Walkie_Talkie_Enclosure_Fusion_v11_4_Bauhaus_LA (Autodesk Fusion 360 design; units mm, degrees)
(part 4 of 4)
sketch "Action Button Retaining Ring" plane through (0, 0, 0) normal (0, 0, 1) x axis (1, 0, 0)
  line L1 (4.3, -61.5) -> (-4.3, -61.5)
  line L2 (14.5, -42.7) -> (14.5, -51.3)
  line L3 (-4.3, -32.5) -> (4.3, -32.5)
  line L4 (-14.5, -51.3) -> (-14.5, -42.7)
  line L5 (4.55, -58.8) -> (-4.55, -58.8)
  line L6 (11.8, -42.45) -> (11.8, -51.55)
  line L7 (-4.55, -35.2) -> (4.55, -35.2)
  line L8 (-11.8, -51.55) -> (-11.8, -42.45)
  arc A1 centre (4.3, -51.3) radius 10.2 clockwise from (14.5, -51.3) to (4.3, -61.5)
  arc A2 centre (4.3, -42.7) radius 10.2 clockwise from (4.3, -32.5) to (14.5, -42.7)
  arc A3 centre (-4.3, -42.7) radius 10.2 clockwise from (-14.5, -42.7) to (-4.3, -32.5)
  arc A4 centre (-4.3, -51.3) radius 10.2 clockwise from (-4.3, -61.5) to (-14.5, -51.3)
  arc A5 centre (4.55, -51.55) radius 7.25 clockwise from (11.8, -51.55) to (4.55, -58.8)
  arc A6 centre (4.55, -42.45) radius 7.25 clockwise from (4.55, -35.2) to (11.8, -42.45)
  arc A7 centre (-4.55, -42.45) radius 7.25 clockwise from (-11.8, -42.45) to (-4.55, -35.2)
  arc A8 centre (-4.55, -51.55) radius 7.25 clockwise from (-4.55, -58.8) to (-11.8, -51.55)
extrude "Extrude3" add sketch "Action Button Retaining Ring" blind 0.5 from offset 2.3
sketch "Sketch4" plane through (0, 0, 0) normal (0, 0, 1) x axis (1, 0, 0)
  circle C1 centre (0, -47) radius 2.5
extrude "Extrude4" add sketch "Sketch4" blind 0.4 from offset 2.25
sketch "Raised Action Mark" plane through (0, 0, 0) normal (0, 0, 1) x axis (1, 0, 0)
  line L1 (3.4, -42.8) -> (3.4, -51.2)
  line L2 (-4.2, -47) -> (3.4, -42.8)
  line L3 (3.4, -51.2) -> (-4.2, -47)
extrude "Extrude5" cut sketch "Raised Action Mark" blind 0.42 from offset -0.6
sketch "Status Light Diffuser Sketch" plane through (0, 0, 0) normal (0, 0, 1) x axis (1, 0, 0)
  line L1 (0.05, 0.1) -> (-0.05, 0.1)
  line L2 (1.9, 8.05) -> (1.9, 1.95)
  line L3 (-0.05, 9.9) -> (0.05, 9.9)
  line L4 (-1.9, 1.95) -> (-1.9, 8.05)
  arc A1 centre (0.05, 1.95) radius 1.85 clockwise from (1.9, 1.95) to (0.05, 0.1)
  arc A2 centre (0.05, 8.05) radius 1.85 clockwise from (0.05, 9.9) to (1.9, 8.05)
  arc A3 centre (-0.05, 8.05) radius 1.85 clockwise from (-1.9, 8.05) to (-0.05, 9.9)
  arc A4 centre (-0.05, 1.95) radius 1.85 clockwise from (-0.05, 0.1) to (-1.9, 1.95)
extrude "Extrude1" new body sketch "Status Light Diffuser Sketch" blind 2.82 from offset -0.42
fillet "Fillet1" radius 0.65
sketch "Status Light Collector Sketch" plane through (0, 0, 0) normal (0, 0, 1) x axis (1, 0, 0)
  circle C1 centre (0, 5) radius 2.7
extrude "Extrude2" add sketch "Status Light Collector Sketch" blind 1.35 from offset 2.15
sketch "Front Switch Clamp Plate Sketch" plane through (0, 0, 0) normal (0, 0, 1) x axis (1, 0, 0)
  line L1 (17, -54) -> (-17, -54)
  line L2 (20, -43) -> (20, -51)
  line L3 (-17, -40) -> (17, -40)
  line L4 (-20, -51) -> (-20, -43)
  line L5 (3, -50.5) -> (-3, -50.5)
  line L6 (4.5, -45) -> (4.5, -49)
  line L7 (-3, -43.5) -> (3, -43.5)
  line L8 (-4.5, -49) -> (-4.5, -45)
  arc A1 centre (17, -51) radius 3 clockwise from (20, -51) to (17, -54)
  arc A2 centre (17, -43) radius 3 clockwise from (17, -40) to (20, -43)
  arc A3 centre (-17, -43) radius 3 clockwise from (-20, -43) to (-17, -40)
  arc A4 centre (-17, -51) radius 3 clockwise from (-17, -54) to (-20, -51)
  arc A5 centre (3, -49) radius 1.5 clockwise from (4.5, -49) to (3, -50.5)
  arc A6 centre (3, -45) radius 1.5 clockwise from (3, -43.5) to (4.5, -45)
  arc A7 centre (-3, -45) radius 1.5 clockwise from (-4.5, -45) to (-3, -43.5)
  arc A8 centre (-3, -49) radius 1.5 clockwise from (-3, -50.5) to (-4.5, -49)
extrude "Extrude1" new body sketch "Front Switch Clamp Plate Sketch" blind 1.4 from offset 10.9
sketch "Front Switch Corner Guide Sketch" plane through (0, 0, 0) normal (0, 0, 1) x axis (1, 0, 0)
  line L1 (-6.65, -55) -> (-7.55, -55)
  line L2 (-6.2, -53.65) -> (-6.2, -54.55)
  line L3 (-7.55, -53.2) -> (-6.65, -53.2)
  line L4 (-8, -54.55) -> (-8, -53.65)
  arc A1 centre (-6.65, -54.55) radius 0.45 clockwise from (-6.2, -54.55) to (-6.65, -55)
  arc A2 centre (-6.65, -53.65) radius 0.45 clockwise from (-6.65, -53.2) to (-6.2, -53.65)
  arc A3 centre (-7.55, -53.65) radius 0.45 clockwise from (-8, -53.65) to (-7.55, -53.2)
  arc A4 centre (-7.55, -54.55) radius 0.45 clockwise from (-7.55, -55) to (-8, -54.55)
extrude "Extrude2" add sketch "Front Switch Corner Guide Sketch" blind 7.25 from offset 3.65
sketch "Front Switch Corner Guide Sketch (1)" plane through (0, 0, 0) normal (0, 0, 1) x axis (1, 0, 0)
  line L1 (-6.65, -40.8) -> (-7.55, -40.8)
  line L2 (-6.2, -39.45) -> (-6.2, -40.35)
  line L3 (-7.55, -39) -> (-6.65, -39)
  line L4 (-8, -40.35) -> (-8, -39.45)
  arc A1 centre (-6.65, -40.35) radius 0.45 clockwise from (-6.2, -40.35) to (-6.65, -40.8)
  arc A2 centre (-6.65, -39.45) radius 0.45 clockwise from (-6.65, -39) to (-6.2, -39.45)
  arc A3 centre (-7.55, -39.45) radius 0.45 clockwise from (-8, -39.45) to (-7.55, -39)
  arc A4 centre (-7.55, -40.35) radius 0.45 clockwise from (-7.55, -40.8) to (-8, -40.35)
extrude "Extrude3" add sketch "Front Switch Corner Guide Sketch (1)" blind 7.25 from offset 3.65
sketch "Front Switch Corner Guide Sketch (2)" plane through (0, 0, 0) normal (0, 0, 1) x axis (1, 0, 0)
  line L1 (7.55, -55) -> (6.65, -55)
  line L2 (8, -53.65) -> (8, -54.55)
  line L3 (6.65, -53.2) -> (7.55, -53.2)
  line L4 (6.2, -54.55) -> (6.2, -53.65)
  arc A1 centre (7.55, -54.55) radius 0.45 clockwise from (8, -54.55) to (7.55, -55)
  arc A2 centre (7.55, -53.65) radius 0.45 clockwise from (7.55, -53.2) to (8, -53.65)
  arc A3 centre (6.65, -53.65) radius 0.45 clockwise from (6.2, -53.65) to (6.65, -53.2)
  arc A4 centre (6.65, -54.55) radius 0.45 clockwise from (6.65, -55) to (6.2, -54.55)
extrude "Extrude4" add sketch "Front Switch Corner Guide Sketch (2)" blind 7.25 from offset 3.65
sketch "Front Switch Corner Guide Sketch (3)" plane through (0, 0, 0) normal (0, 0, 1) x axis (1, 0, 0)
  line L1 (7.55, -40.8) -> (6.65, -40.8)
  line L2 (8, -39.45) -> (8, -40.35)
  line L3 (6.65, -39) -> (7.55, -39)
  line L4 (6.2, -40.35) -> (6.2, -39.45)
  arc A1 centre (7.55, -40.35) radius 0.45 clockwise from (8, -40.35) to (7.55, -40.8)
  arc A2 centre (7.55, -39.45) radius 0.45 clockwise from (7.55, -39) to (8, -39.45)
  arc A3 centre (6.65, -39.45) radius 0.45 clockwise from (6.2, -39.45) to (6.65, -39)
  arc A4 centre (6.65, -40.35) radius 0.45 clockwise from (6.65, -40.8) to (6.2, -40.35)
extrude "Extrude5" add sketch "Front Switch Corner Guide Sketch (3)" blind 7.25 from offset 3.65
sketch "Front Switch Clamp M2 Clearance Sketch" plane through (0, 0, 0) normal (0, 0, 1) x axis (1, 0, 0)
  circle C1 centre (-17, -47) radius 1.3
extrude "Extrude6" cut sketch "Front Switch Clamp M2 Clearance Sketch" blind 2.2 from offset 10.5
sketch "Front Switch Clamp M2 Clearance Sketch (1)" plane through (0, 0, 0) normal (0, 0, 1) x axis (1, 0, 0)
  circle C1 centre (17, -47) radius 1.3
extrude "Extrude7" cut sketch "Front Switch Clamp M2 Clearance Sketch (1)" blind 2.2 from offset 10.5
sketch "LEFT PTT BUTTON Cap Sketch" plane through (0, 0, 0) normal (1, 0, 0) x axis (0, 0, -1)
  line L1 (-14.65, -15) -> (-14.85, -15)
  line L2 (-8.75, 33.1) -> (-8.75, -9.1)
  line L3 (-14.85, 39) -> (-14.65, 39)
  line L4 (-20.75, -9.1) -> (-20.75, 33.1)
  arc A1 centre (-14.65, -9.1) radius 5.9 clockwise from (-8.75, -9.1) to (-14.65, -15)
  arc A2 centre (-14.65, 33.1) radius 5.9 clockwise from (-14.65, 39) to (-8.75, 33.1)
  arc A3 centre (-14.85, 33.1) radius 5.9 clockwise from (-20.75, 33.1) to (-14.85, 39)
  arc A4 centre (-14.85, -9.1) radius 5.9 clockwise from (-14.85, -15) to (-20.75, -9.1)
extrude "Extrude1" new body sketch "LEFT PTT BUTTON Cap Sketch" blind -1.7 (= "-( 1.70 mm )") from offset 41
fillet "Fillet1" radius 1.2
sketch "LEFT PTT BUTTON End Guide Shoe Sketch" plane through (0, 0, 0) normal (1, 0, 0) x axis (0, 0, -1)
  line L1 (-10.95, -8.6) -> (-18.55, -8.6)
  line L2 (-10.45, -7.9) -> (-10.45, -8.1)
  line L3 (-18.55, -7.4) -> (-10.95, -7.4)
  line L4 (-19.05, -8.1) -> (-19.05, -7.9)
  arc A1 centre (-10.95, -8.1) radius 0.5 clockwise from (-10.45, -8.1) to (-10.95, -8.6)
  arc A2 centre (-10.95, -7.9) radius 0.5 clockwise from (-10.95, -7.4) to (-10.45, -7.9)
  arc A3 centre (-18.55, -7.9) radius 0.5 clockwise from (-19.05, -7.9) to (-18.55, -7.4)
  arc A4 centre (-18.55, -8.1) radius 0.5 clockwise from (-18.55, -8.6) to (-19.05, -8.1)
extrude "Extrude2" add sketch "LEFT PTT BUTTON End Guide Shoe Sketch" blind 3 from offset 36.5
sketch "LEFT PTT BUTTON Captive End Flange Sketch" plane through (0, 0, 0) normal (1, 0, 0) x axis (0, 0, -1)
  line L1 (-10.95, -9.2) -> (-18.55, -9.2)
  line L2 (-10.05, -7.7) -> (-10.05, -8.3)
  line L3 (-18.55, -6.8) -> (-10.95, -6.8)
  line L4 (-19.45, -8.3) -> (-19.45, -7.7)
  arc A1 centre (-10.95, -8.3) radius 0.9 clockwise from (-10.05, -8.3) to (-10.95, -9.2)
  arc A2 centre (-10.95, -7.7) radius 0.9 clockwise from (-10.95, -6.8) to (-10.05, -7.7)
  arc A3 centre (-18.55, -7.7) radius 0.9 clockwise from (-19.45, -7.7) to (-18.55, -6.8)
  arc A4 centre (-18.55, -8.3) radius 0.9 clockwise from (-18.55, -9.2) to (-19.45, -8.3)
extrude "Extrude3" add sketch "LEFT PTT BUTTON Captive End Flange Sketch" blind 1.05 from offset 35.5
sketch "LEFT PTT BUTTON End Guide Shoe Sketch (1)" plane through (0, 0, 0) normal (1, 0, 0) x axis (0, 0, -1)
  line L1 (-10.95, 31.4) -> (-18.55, 31.4)
  line L2 (-10.45, 32.1) -> (-10.45, 31.9)
  line L3 (-18.55, 32.6) -> (-10.95, 32.6)
  line L4 (-19.05, 31.9) -> (-19.05, 32.1)
  arc A1 centre (-10.95, 31.9) radius 0.5 clockwise from (-10.45, 31.9) to (-10.95, 31.4)
  arc A2 centre (-10.95, 32.1) radius 0.5 clockwise from (-10.95, 32.6) to (-10.45, 32.1)
  arc A3 centre (-18.55, 32.1) radius 0.5 clockwise from (-19.05, 32.1) to (-18.55, 32.6)
  arc A4 centre (-18.55, 31.9) radius 0.5 clockwise from (-18.55, 31.4) to (-19.05, 31.9)
extrude "Extrude4" add sketch "LEFT PTT BUTTON End Guide Shoe Sketch (1)" blind 3 from offset 36.5
sketch "LEFT PTT BUTTON Captive End Flange Sketch (1)" plane through (0, 0, 0) normal (1, 0, 0) x axis (0, 0, -1)
  line L1 (-10.95, 30.8) -> (-18.55, 30.8)
  line L2 (-10.05, 32.3) -> (-10.05, 31.7)
  line L3 (-18.55, 33.2) -> (-10.95, 33.2)
  line L4 (-19.45, 31.7) -> (-19.45, 32.3)
  arc A1 centre (-10.95, 31.7) radius 0.9 clockwise from (-10.05, 31.7) to (-10.95, 30.8)
  arc A2 centre (-10.95, 32.3) radius 0.9 clockwise from (-10.95, 33.2) to (-10.05, 32.3)
  arc A3 centre (-18.55, 32.3) radius 0.9 clockwise from (-19.45, 32.3) to (-18.55, 33.2)
  arc A4 centre (-18.55, 31.7) radius 0.9 clockwise from (-18.55, 30.8) to (-19.45, 31.7)
extrude "Extrude5" add sketch "LEFT PTT BUTTON Captive End Flange Sketch (1)" blind 1.05 from offset 35.5
sketch "LEFT PTT BUTTON Center Actuator Pusher Sketch" plane through (0, 0, 0) normal (1, 0, 0) x axis (0, 0, -1)
  line L1 (-16.35, 11) -> (-17.05, 11)
  line L2 (-15.7, 12.35) -> (-15.7, 11.65)
  line L3 (-17.05, 13) -> (-16.35, 13)
  line L4 (-17.7, 11.65) -> (-17.7, 12.35)
  arc A1 centre (-16.35, 11.65) radius 0.65 clockwise from (-15.7, 11.65) to (-16.35, 11)
  arc A2 centre (-16.35, 12.35) radius 0.65 clockwise from (-16.35, 13) to (-15.7, 12.35)
  arc A3 centre (-17.05, 12.35) radius 0.65 clockwise from (-17.7, 12.35) to (-17.05, 13)
  arc A4 centre (-17.05, 11.65) radius 0.65 clockwise from (-17.05, 11) to (-17.7, 11.65)
extrude "Extrude6" add sketch "LEFT PTT BUTTON Center Actuator Pusher Sketch" blind 0.8 from offset 38.65
sketch "PTT Tactile Rib 01 Sketch" plane through (0, 0, 0) normal (1, 0, 0) x axis (0, 0, -1)
  line L1 (-18.33, -11) -> (-18.37, -11)
  line L2 (-18.14, 34.81) -> (-18.14, -10.81)
  line L3 (-18.37, 35) -> (-18.33, 35)
  line L4 (-18.56, -10.81) -> (-18.56, 34.81)
  arc A1 centre (-18.33, -10.81) radius 0.19 clockwise from (-18.14, -10.81) to (-18.33, -11)
  arc A2 centre (-18.33, 34.81) radius 0.19 clockwise from (-18.33, 35) to (-18.14, 34.81)
  arc A3 centre (-18.37, 34.81) radius 0.19 clockwise from (-18.56, 34.81) to (-18.37, 35)
  arc A4 centre (-18.37, -10.81) radius 0.19 clockwise from (-18.37, -11) to (-18.56, -10.81)
extrude "Extrude7" add sketch "PTT Tactile Rib 01 Sketch" blind 0.32 from offset 40.95
sketch "PTT Tactile Rib 02 Sketch" plane through (0, 0, 0) normal (1, 0, 0) x axis (0, 0, -1)
  line L1 (-16.53, -11) -> (-16.57, -11)
  line L2 (-16.34, 34.81) -> (-16.34, -10.81)
  line L3 (-16.57, 35) -> (-16.53, 35)
  line L4 (-16.76, -10.81) -> (-16.76, 34.81)
  arc A1 centre (-16.53, -10.81) radius 0.19 clockwise from (-16.34, -10.81) to (-16.53, -11)
  arc A2 centre (-16.53, 34.81) radius 0.19 clockwise from (-16.53, 35) to (-16.34, 34.81)
  arc A3 centre (-16.57, 34.81) radius 0.19 clockwise from (-16.76, 34.81) to (-16.57, 35)
  arc A4 centre (-16.57, -10.81) radius 0.19 clockwise from (-16.57, -11) to (-16.76, -10.81)
extrude "Extrude8" add sketch "PTT Tactile Rib 02 Sketch" blind 0.32 from offset 40.95
sketch "PTT Tactile Rib 03 Sketch" plane through (0, 0, 0) normal (1, 0, 0) x axis (0, 0, -1)
  line L1 (-14.73, -11) -> (-14.77, -11)
  line L2 (-14.54, 34.81) -> (-14.54, -10.81)
  line L3 (-14.77, 35) -> (-14.73, 35)
  line L4 (-14.96, -10.81) -> (-14.96, 34.81)
  arc A1 centre (-14.73, -10.81) radius 0.19 clockwise from (-14.54, -10.81) to (-14.73, -11)
  arc A2 centre (-14.73, 34.81) radius 0.19 clockwise from (-14.73, 35) to (-14.54, 34.81)
  arc A3 centre (-14.77, 34.81) radius 0.19 clockwise from (-14.96, 34.81) to (-14.77, 35)
  arc A4 centre (-14.77, -10.81) radius 0.19 clockwise from (-14.77, -11) to (-14.96, -10.81)
extrude "Extrude9" add sketch "PTT Tactile Rib 03 Sketch" blind 0.32 from offset 40.95
sketch "PTT Tactile Rib 04 Sketch" plane through (0, 0, 0) normal (1, 0, 0) x axis (0, 0, -1)
  line L1 (-12.93, -11) -> (-12.97, -11)
  line L2 (-12.74, 34.81) -> (-12.74, -10.81)
  line L3 (-12.97, 35) -> (-12.93, 35)
  line L4 (-13.16, -10.81) -> (-13.16, 34.81)
  arc A1 centre (-12.93, -10.81) radius 0.19 clockwise from (-12.74, -10.81) to (-12.93, -11)
  arc A2 centre (-12.93, 34.81) radius 0.19 clockwise from (-12.93, 35) to (-12.74, 34.81)
  arc A3 centre (-12.97, 34.81) radius 0.19 clockwise from (-13.16, 34.81) to (-12.97, 35)
  arc A4 centre (-12.97, -10.81) radius 0.19 clockwise from (-12.97, -11) to (-13.16, -10.81)
extrude "Extrude10" add sketch "PTT Tactile Rib 04 Sketch" blind 0.32 from offset 40.95
sketch "PTT Tactile Rib 05 Sketch" plane through (0, 0, 0) normal (1, 0, 0) x axis (0, 0, -1)
  line L1 (-11.13, -11) -> (-11.17, -11)
  line L2 (-10.94, 34.81) -> (-10.94, -10.81)
  line L3 (-11.17, 35) -> (-11.13, 35)
  line L4 (-11.36, -10.81) -> (-11.36, 34.81)
  arc A1 centre (-11.13, -10.81) radius 0.19 clockwise from (-10.94, -10.81) to (-11.13, -11)
  arc A2 centre (-11.13, 34.81) radius 0.19 clockwise from (-11.13, 35) to (-10.94, 34.81)
  arc A3 centre (-11.17, 34.81) radius 0.19 clockwise from (-11.36, 34.81) to (-11.17, 35)
  arc A4 centre (-11.17, -10.81) radius 0.19 clockwise from (-11.17, -11) to (-11.36, -10.81)
extrude "Extrude11" add sketch "PTT Tactile Rib 05 Sketch" blind 0.32 from offset 40.95
sketch "VOLUME UP BUTTON Cap Sketch" plane through (0, 0, 0) normal (1, 0, 0) x axis (0, 0, -1)
  line L1 (-14.65, 13.6) -> (-14.85, 13.6)
  line L2 (-9.25, 27) -> (-9.25, 19)
  line L3 (-14.85, 32.4) -> (-14.65, 32.4)
  line L4 (-20.25, 19) -> (-20.25, 27)
  arc A1 centre (-14.65, 19) radius 5.4 clockwise from (-9.25, 19) to (-14.65, 13.6)
  arc A2 centre (-14.65, 27) radius 5.4 clockwise from (-14.65, 32.4) to (-9.25, 27)
  arc A3 centre (-14.85, 27) radius 5.4 clockwise from (-20.25, 27) to (-14.85, 32.4)
  arc A4 centre (-14.85, 19) radius 5.4 clockwise from (-14.85, 13.6) to (-20.25, 19)
extrude "Extrude1" new body sketch "VOLUME UP BUTTON Cap Sketch" blind 1.7 from offset -41
fillet "Fillet1" radius 1.2
sketch "VOLUME UP BUTTON End Guide Shoe Sketch" plane through (0, 0, 0) normal (1, 0, 0) x axis (0, 0, -1)
  line L1 (-13.25, 15.6) -> (-16.25, 15.6)
  line L2 (-12.75, 16.3) -> (-12.75, 16.1)
  line L3 (-16.25, 16.8) -> (-13.25, 16.8)
  line L4 (-16.75, 16.1) -> (-16.75, 16.3)
  arc A1 centre (-13.25, 16.1) radius 0.5 clockwise from (-12.75, 16.1) to (-13.25, 15.6)
  arc A2 centre (-13.25, 16.3) radius 0.5 clockwise from (-13.25, 16.8) to (-12.75, 16.3)
  arc A3 centre (-16.25, 16.3) radius 0.5 clockwise from (-16.75, 16.3) to (-16.25, 16.8)
  arc A4 centre (-16.25, 16.1) radius 0.5 clockwise from (-16.25, 15.6) to (-16.75, 16.1)
extrude "Extrude2" add sketch "VOLUME UP BUTTON End Guide Shoe Sketch" blind 3 from offset -39.5
sketch "VOLUME UP BUTTON Captive End Flange Sketch" plane through (0, 0, 0) normal (1, 0, 0) x axis (0, 0, -1)
  line L1 (-12.75, 15) -> (-16.75, 15)
  line L2 (-11.85, 16.5) -> (-11.85, 15.9)
  line L3 (-16.75, 17.4) -> (-12.75, 17.4)
  line L4 (-17.65, 15.9) -> (-17.65, 16.5)
  arc A1 centre (-12.75, 15.9) radius 0.9 clockwise from (-11.85, 15.9) to (-12.75, 15)
  arc A2 centre (-12.75, 16.5) radius 0.9 clockwise from (-12.75, 17.4) to (-11.85, 16.5)
  arc A3 centre (-16.75, 16.5) radius 0.9 clockwise from (-17.65, 16.5) to (-16.75, 17.4)
  arc A4 centre (-16.75, 15.9) radius 0.9 clockwise from (-16.75, 15) to (-17.65, 15.9)
extrude "Extrude3" add sketch "VOLUME UP BUTTON Captive End Flange Sketch" blind 1.05 from offset -36.55
sketch "VOLUME UP BUTTON End Guide Shoe Sketch (1)" plane through (0, 0, 0) normal (1, 0, 0) x axis (0, 0, -1)
  line L1 (-13.25, 29.2) -> (-16.25, 29.2)
  line L2 (-12.75, 29.9) -> (-12.75, 29.7)
  line L3 (-16.25, 30.4) -> (-13.25, 30.4)
  line L4 (-16.75, 29.7) -> (-16.75, 29.9)
  arc A1 centre (-13.25, 29.7) radius 0.5 clockwise from (-12.75, 29.7) to (-13.25, 29.2)
  arc A2 centre (-13.25, 29.9) radius 0.5 clockwise from (-13.25, 30.4) to (-12.75, 29.9)
  arc A3 centre (-16.25, 29.9) radius 0.5 clockwise from (-16.75, 29.9) to (-16.25, 30.4)
  arc A4 centre (-16.25, 29.7) radius 0.5 clockwise from (-16.25, 29.2) to (-16.75, 29.7)
extrude "Extrude4" add sketch "VOLUME UP BUTTON End Guide Shoe Sketch (1)" blind 3 from offset -39.5
sketch "VOLUME UP BUTTON Captive End Flange Sketch (1)" plane through (0, 0, 0) normal (1, 0, 0) x axis (0, 0, -1)
  line L1 (-12.75, 28.6) -> (-16.75, 28.6)
  line L2 (-11.85, 30.1) -> (-11.85, 29.5)
  line L3 (-16.75, 31) -> (-12.75, 31)
  line L4 (-17.65, 29.5) -> (-17.65, 30.1)
  arc A1 centre (-12.75, 29.5) radius 0.9 clockwise from (-11.85, 29.5) to (-12.75, 28.6)
  arc A2 centre (-12.75, 30.1) radius 0.9 clockwise from (-12.75, 31) to (-11.85, 30.1)
  arc A3 centre (-16.75, 30.1) radius 0.9 clockwise from (-17.65, 30.1) to (-16.75, 31)
  arc A4 centre (-16.75, 29.5) radius 0.9 clockwise from (-16.75, 28.6) to (-17.65, 29.5)
extrude "Extrude5" add sketch "VOLUME UP BUTTON Captive End Flange Sketch (1)" blind 1.05 from offset -36.55
sketch "VOLUME UP BUTTON Center Actuator Pusher Sketch" plane through (0, 0, 0) normal (1, 0, 0) x axis (0, 0, -1)
  line L1 (-16.35, 22) -> (-17.05, 22)
  line L2 (-15.7, 23.35) -> (-15.7, 22.65)
  line L3 (-17.05, 24) -> (-16.35, 24)
  line L4 (-17.7, 22.65) -> (-17.7, 23.35)
  arc A1 centre (-16.35, 22.65) radius 0.65 clockwise from (-15.7, 22.65) to (-16.35, 22)
  arc A2 centre (-16.35, 23.35) radius 0.65 clockwise from (-16.35, 24) to (-15.7, 23.35)
  arc A3 centre (-17.05, 23.35) radius 0.65 clockwise from (-17.7, 23.35) to (-17.05, 24)
  arc A4 centre (-17.05, 22.65) radius 0.65 clockwise from (-17.05, 22) to (-17.7, 22.65)
extrude "Extrude6" add sketch "VOLUME UP BUTTON Center Actuator Pusher Sketch" blind 0.8 from offset -39.45
sketch "Volume Plus Horizontal Sketch" plane through (0, 0, 0) normal (1, 0, 0) x axis (0, 0, -1)
  line L1 (-14.7, 20) -> (-14.8, 20)
  line L2 (-14.25, 25.55) -> (-14.25, 20.45)
  line L3 (-14.8, 26) -> (-14.7, 26)
  line L4 (-15.25, 20.45) -> (-15.25, 25.55)
  arc A1 centre (-14.7, 20.45) radius 0.45 clockwise from (-14.25, 20.45) to (-14.7, 20)
  arc A2 centre (-14.7, 25.55) radius 0.45 clockwise from (-14.7, 26) to (-14.25, 25.55)
  arc A3 centre (-14.8, 25.55) radius 0.45 clockwise from (-15.25, 25.55) to (-14.8, 26)
  arc A4 centre (-14.8, 20.45) radius 0.45 clockwise from (-14.8, 20) to (-15.25, 20.45)
extrude "Extrude7" add sketch "Volume Plus Horizontal Sketch" blind -0.55 (= "-( 0.55 mm )") from offset -40.9
sketch "Volume Plus Vertical Sketch" plane through (0, 0, 0) normal (1, 0, 0) x axis (0, 0, -1)
  line L1 (-12.2, 22.5) -> (-17.3, 22.5)
  line L2 (-11.75, 23.05) -> (-11.75, 22.95)
  line L3 (-17.3, 23.5) -> (-12.2, 23.5)
  line L4 (-17.75, 22.95) -> (-17.75, 23.05)
  arc A1 centre (-12.2, 22.95) radius 0.45 clockwise from (-11.75, 22.95) to (-12.2, 22.5)
  arc A2 centre (-12.2, 23.05) radius 0.45 clockwise from (-12.2, 23.5) to (-11.75, 23.05)
  arc A3 centre (-17.3, 23.05) radius 0.45 clockwise from (-17.75, 23.05) to (-17.3, 23.5)
  arc A4 centre (-17.3, 22.95) radius 0.45 clockwise from (-17.3, 22.5) to (-17.75, 22.95)
extrude "Extrude8" add sketch "Volume Plus Vertical Sketch" blind -0.55 (= "-( 0.55 mm )") from offset -40.9
sketch "VOLUME DOWN BUTTON Cap Sketch" plane through (0, 0, 0) normal (1, 0, 0) x axis (0, 0, -1)
  line L1 (-14.65, -15.4) -> (-14.85, -15.4)
  line L2 (-9.25, -2) -> (-9.25, -10)
  line L3 (-14.85, 3.4) -> (-14.65, 3.4)
  line L4 (-20.25, -10) -> (-20.25, -2)
  arc A1 centre (-14.65, -10) radius 5.4 clockwise from (-9.25, -10) to (-14.65, -15.4)
  arc A2 centre (-14.65, -2) radius 5.4 clockwise from (-14.65, 3.4) to (-9.25, -2)
  arc A3 centre (-14.85, -2) radius 5.4 clockwise from (-20.25, -2) to (-14.85, 3.4)
  arc A4 centre (-14.85, -10) radius 5.4 clockwise from (-14.85, -15.4) to (-20.25, -10)
extrude "Extrude1" new body sketch "VOLUME DOWN BUTTON Cap Sketch" blind 1.7 from offset -41
fillet "Fillet1" radius 1.2
sketch "VOLUME DOWN BUTTON End Guide Shoe Sketch" plane through (0, 0, 0) normal (1, 0, 0) x axis (0, 0, -1)
  line L1 (-13.25, -13.4) -> (-16.25, -13.4)
  line L2 (-12.75, -12.7) -> (-12.75, -12.9)
  line L3 (-16.25, -12.2) -> (-13.25, -12.2)
  line L4 (-16.75, -12.9) -> (-16.75, -12.7)
  arc A1 centre (-13.25, -12.9) radius 0.5 clockwise from (-12.75, -12.9) to (-13.25, -13.4)
  arc A2 centre (-13.25, -12.7) radius 0.5 clockwise from (-13.25, -12.2) to (-12.75, -12.7)
  arc A3 centre (-16.25, -12.7) radius 0.5 clockwise from (-16.75, -12.7) to (-16.25, -12.2)
  arc A4 centre (-16.25, -12.9) radius 0.5 clockwise from (-16.25, -13.4) to (-16.75, -12.9)
extrude "Extrude2" add sketch "VOLUME DOWN BUTTON End Guide Shoe Sketch" blind 3 from offset -39.5
sketch "VOLUME DOWN BUTTON Captive End Flange Sketch" plane through (0, 0, 0) normal (1, 0, 0) x axis (0, 0, -1)
  line L1 (-12.75, -14) -> (-16.75, -14)
  line L2 (-11.85, -12.5) -> (-11.85, -13.1)
  line L3 (-16.75, -11.6) -> (-12.75, -11.6)
  line L4 (-17.65, -13.1) -> (-17.65, -12.5)
  arc A1 centre (-12.75, -13.1) radius 0.9 clockwise from (-11.85, -13.1) to (-12.75, -14)
  arc A2 centre (-12.75, -12.5) radius 0.9 clockwise from (-12.75, -11.6) to (-11.85, -12.5)
  arc A3 centre (-16.75, -12.5) radius 0.9 clockwise from (-17.65, -12.5) to (-16.75, -11.6)
  arc A4 centre (-16.75, -13.1) radius 0.9 clockwise from (-16.75, -14) to (-17.65, -13.1)
extrude "Extrude3" add sketch "VOLUME DOWN BUTTON Captive End Flange Sketch" blind 1.05 from offset -36.55
sketch "VOLUME DOWN BUTTON End Guide Shoe Sketch (1)" plane through (0, 0, 0) normal (1, 0, 0) x axis (0, 0, -1)
  line L1 (-13.25, 0.2) -> (-16.25, 0.2)
  line L2 (-12.75, 0.9) -> (-12.75, 0.7)
  line L3 (-16.25, 1.4) -> (-13.25, 1.4)
  line L4 (-16.75, 0.7) -> (-16.75, 0.9)
  arc A1 centre (-13.25, 0.7) radius 0.5 clockwise from (-12.75, 0.7) to (-13.25, 0.2)
  arc A2 centre (-13.25, 0.9) radius 0.5 clockwise from (-13.25, 1.4) to (-12.75, 0.9)
  arc A3 centre (-16.25, 0.9) radius 0.5 clockwise from (-16.75, 0.9) to (-16.25, 1.4)
  arc A4 centre (-16.25, 0.7) radius 0.5 clockwise from (-16.25, 0.2) to (-16.75, 0.7)
extrude "Extrude4" add sketch "VOLUME DOWN BUTTON End Guide Shoe Sketch (1)" blind 3 from offset -39.5
sketch "VOLUME DOWN BUTTON Captive End Flange Sketch (1)" plane through (0, 0, 0) normal (1, 0, 0) x axis (0, 0, -1)
  line L1 (-12.75, -0.4) -> (-16.75, -0.4)
  line L2 (-11.85, 1.1) -> (-11.85, 0.5)
  line L3 (-16.75, 2) -> (-12.75, 2)
  line L4 (-17.65, 0.5) -> (-17.65, 1.1)
  arc A1 centre (-12.75, 0.5) radius 0.9 clockwise from (-11.85, 0.5) to (-12.75, -0.4)
  arc A2 centre (-12.75, 1.1) radius 0.9 clockwise from (-12.75, 2) to (-11.85, 1.1)
  arc A3 centre (-16.75, 1.1) radius 0.9 clockwise from (-17.65, 1.1) to (-16.75, 2)
  arc A4 centre (-16.75, 0.5) radius 0.9 clockwise from (-16.75, -0.4) to (-17.65, 0.5)
extrude "Extrude5" add sketch "VOLUME DOWN BUTTON Captive End Flange Sketch (1)" blind 1.05 from offset -36.55
sketch "VOLUME DOWN BUTTON Center Actuator Pusher Sketch" plane through (0, 0, 0) normal (1, 0, 0) x axis (0, 0, -1)
  line L1 (-16.35, -7) -> (-17.05, -7)
  line L2 (-15.7, -5.65) -> (-15.7, -6.35)
  line L3 (-17.05, -5) -> (-16.35, -5)
  line L4 (-17.7, -6.35) -> (-17.7, -5.65)
  arc A1 centre (-16.35, -6.35) radius 0.65 clockwise from (-15.7, -6.35) to (-16.35, -7)
  arc A2 centre (-16.35, -5.65) radius 0.65 clockwise from (-16.35, -5) to (-15.7, -5.65)
  arc A3 centre (-17.05, -5.65) radius 0.65 clockwise from (-17.7, -5.65) to (-17.05, -5)
  arc A4 centre (-17.05, -6.35) radius 0.65 clockwise from (-17.05, -7) to (-17.7, -6.35)
extrude "Extrude6" add sketch "VOLUME DOWN BUTTON Center Actuator Pusher Sketch" blind 0.8 from offset -39.45
sketch "Volume Minus Sketch" plane through (0, 0, 0) normal (1, 0, 0) x axis (0, 0, -1)
  line L1 (-14.7, -9) -> (-14.8, -9)
  line L2 (-14.25, -3.45) -> (-14.25, -8.55)
  line L3 (-14.8, -3) -> (-14.7, -3)
  line L4 (-15.25, -8.55) -> (-15.25, -3.45)
  arc A1 centre (-14.7, -8.55) radius 0.45 clockwise from (-14.25, -8.55) to (-14.7, -9)
  arc A2 centre (-14.7, -3.45) radius 0.45 clockwise from (-14.7, -3) to (-14.25, -3.45)
  arc A3 centre (-14.8, -3.45) radius 0.45 clockwise from (-15.25, -3.45) to (-14.8, -3)
  arc A4 centre (-14.8, -8.55) radius 0.45 clockwise from (-14.8, -9) to (-15.25, -8.55)
extrude "Extrude7" add sketch "Volume Minus Sketch" blind -0.55 (= "-( 0.55 mm )") from offset -40.9
base_feature "Base Feature1"
base_mesh_feature "Base Mesh Feature1"
base_feature "Base Feature1"
base_mesh_feature "Base Mesh Feature1"
base_feature "Base Feature1"
base_mesh_feature "Base Mesh Feature1"
base_feature "Base Feature1"
base_mesh_feature "Base Mesh Feature1"
base_feature "Base Feature1"
base_mesh_feature "Base Mesh Feature1"
base_feature "Base Feature1"
base_mesh_feature "Base Mesh Feature1"
base_feature "Base Feature1"
base_mesh_feature "Base Mesh Feature1"
base_feature "Base Feature1"
base_mesh_feature "Base Mesh Feature1"
base_feature "Base Feature1"
base_mesh_feature "Base Mesh Feature1"
base_feature "Base Feature1"
base_mesh_feature "Base Mesh Feature1"
base_feature "Base Feature1"
base_mesh_feature "Base Mesh Feature1"
base_feature "Base Feature1"
base_mesh_feature "Base Mesh Feature1"
base_feature "Base Feature1"
base_feature "Base Feature1"
base_feature "Base Feature1"
base_feature "Base Feature1"
base_feature "Base Feature1"
base_feature "Base Feature1"
base_feature "Base Feature1"
base_feature "Base Feature1"
base_feature "Base Feature1"
base_feature "Base Feature1"
base_feature "Base Feature1"
base_feature "Base Feature1"
base_feature "Base Feature1"
base_feature "Base Feature1"
base_feature "Base Feature1"
base_feature "Base Feature1"
base_feature "Base Feature1"
base_feature "Base Feature1"
base_feature "Base Feature1"
base_feature "Base Feature1"
base_feature "Base Feature1"
base_feature "Base Feature1"
base_feature "Base Feature1"
base_feature "Base Feature1"
base_feature "Base Feature1"
base_feature "Base Feature1"
base_feature "Base Feature1"
sketch "USB-C Plug Mating Shell Gauge Sketch" plane through (0, 0, 0) normal (1, 0, 0) x axis (0, 0, -1)
  line L1 (-12.6364, -25.1693) -> (-12.7164, -25.1693)
  line L2 (-11.4464, -18.0493) -> (-11.4464, -23.9793)
  line L3 (-12.7164, -16.8593) -> (-12.6364, -16.8593)
  line L4 (-13.9064, -23.9793) -> (-13.9064, -18.0493)
  arc A1 centre (-12.6364, -23.9793) radius 1.19 clockwise from (-11.4464, -23.9793) to (-12.6364, -25.1693)
  arc A2 centre (-12.6364, -18.0493) radius 1.19 clockwise from (-12.6364, -16.8593) to (-11.4464, -18.0493)
  arc A3 centre (-12.7164, -18.0493) radius 1.19 clockwise from (-13.9064, -18.0493) to (-12.7164, -16.8593)
  arc A4 centre (-12.7164, -23.9793) radius 1.19 clockwise from (-12.7164, -25.1693) to (-13.9064, -23.9793)
extrude "Extrude1" new body sketch "USB-C Plug Mating Shell Gauge Sketch" blind 6.65 from offset 29.8473 bodies "USB-C 6.65 mm Mating Shell"
sketch "USB-C Plug Housing Interface Gauge Sketch" plane through (0, 0, 0) normal (1, 0, 0) x axis (0, 0, -1)
  line L1 (-12.6264, -27.4393) -> (-12.7264, -27.4393)
  line L2 (-9.1764, -18.0393) -> (-9.1764, -23.9893)
  line L3 (-12.7264, -14.5893) -> (-12.6264, -14.5893)
  line L4 (-16.1764, -23.9893) -> (-16.1764, -18.0393)
  arc A1 centre (-12.6264, -23.9893) radius 3.45 clockwise from (-9.1764, -23.9893) to (-12.6264, -27.4393)
  arc A2 centre (-12.6264, -18.0393) radius 3.45 clockwise from (-12.6264, -14.5893) to (-9.1764, -18.0393)
  arc A3 centre (-12.7264, -18.0393) radius 3.45 clockwise from (-16.1764, -18.0393) to (-12.7264, -14.5893)
  arc A4 centre (-12.7264, -23.9893) radius 3.45 clockwise from (-12.7264, -27.4393) to (-16.1764, -23.9893)
extrude "Extrude2" add sketch "USB-C Plug Housing Interface Gauge Sketch" blind 5 from offset 36.2473
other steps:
create_component "CreateComponent1"
create_component "CreateComponent2"
create_component "CreateComponent3"
create_component "CreateComponent4"
create_component "CreateComponent5"
create_component "CreateComponent6"
create_component "CreateComponent7"
create_component "CreateComponent8"
create_component "CreateComponent9"
create_component "CreateComponent10"
create_component "CreateComponent11"
create_component "CreateComponent12"
create_component "CreateComponent13"
create_component "CreateComponent14"
create_component "CreateComponent15"
create_component "CreateComponent16"
create_component "CreateComponent17"
create_component "CreateComponent18"
create_component "CreateComponent19"
create_component "CreateComponent20"
create_component "CreateComponent21"
create_component "CreateComponent1"
create_component "CreateComponent1"
create_component "CreateComponent1"
create_component "CreateComponent2"
create_component "CreateComponent1"
create_component "CreateComponent3"
create_component "CreateComponent1"
create_component "CreateComponent4"
create_component "CreateComponent1"
create_component "CreateComponent5"
create_component "CreateComponent1"
create_component "CreateComponent6"
create_component "CreateComponent1"
create_component "CreateComponent7"
create_component "CreateComponent1"
create_component "CreateComponent8"
create_component "CreateComponent1"
create_component "CreateComponent9"
create_component "CreateComponent1"
create_component "CreateComponent10"
create_component "CreateComponent1"
create_component "CreateComponent11"
create_component "CreateComponent1"
create_component "CreateComponent1"
create_component "CreateComponent2"
create_component "CreateComponent12"
create_component "CreateComponent1"
create_component "CreateComponent13"
create_component "CreateComponent1"
create_component "CreateComponent14"
create_component "CreateComponent1"
create_component "CreateComponent1"
create_component "CreateComponent2"
create_component "CreateComponent15"
create_component "CreateComponent1"
create_component "CreateComponent16"
create_component "CreateComponent1"
create_component "CreateComponent1"
create_component "CreateComponent17"
create_component "CreateComponent1"
create_component "CreateComponent18"
create_component "CreateComponent1"
create_component "CreateComponent1"
create_component "CreateComponent2"
create_component "CreateComponent3"
create_component "CreateComponent4"
create_component "CreateComponent19"
create_component "CreateComponent1"
create_component "CreateComponent20"
create_component "CreateComponent1"
create_component "CreateComponent21"
create_component "CreateComponent1"
create_component "CreateComponent22"
create_component "CreateComponent22"
named bodies: "Front Shell", "Front Cavity Tool", "Back Shell", "Back Cavity Tool", "Front Action Button", "Vertical Status Light Lens", "LEFT PTT BUTTON", "VOLUME UP BUTTON", "VOLUME DOWN BUTTON", "USB-C 6.65 mm Mating Shell"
